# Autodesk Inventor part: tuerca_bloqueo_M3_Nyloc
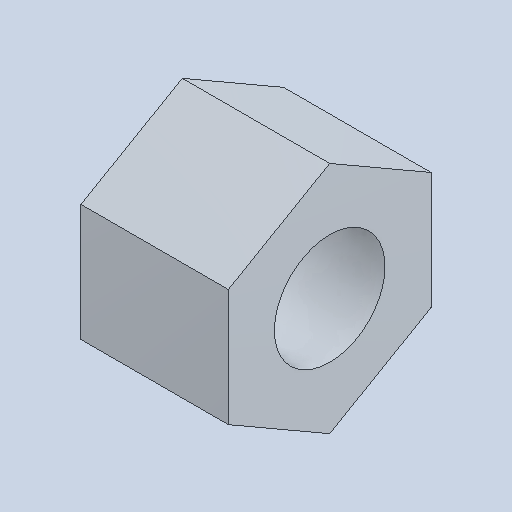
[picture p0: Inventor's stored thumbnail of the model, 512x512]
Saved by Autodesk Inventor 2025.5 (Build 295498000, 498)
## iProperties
Created: 2026-10
Part Number: tuerca_bloqueo_M3_Nyloc
Material: Genérico
Document SubType Name: Modeling
Designer: Luis M
Density: 1 g/cm^3
Appearance: Valor por defecto
Author: Luis M
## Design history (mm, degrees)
feature "Base1"
node "Sólido1"
